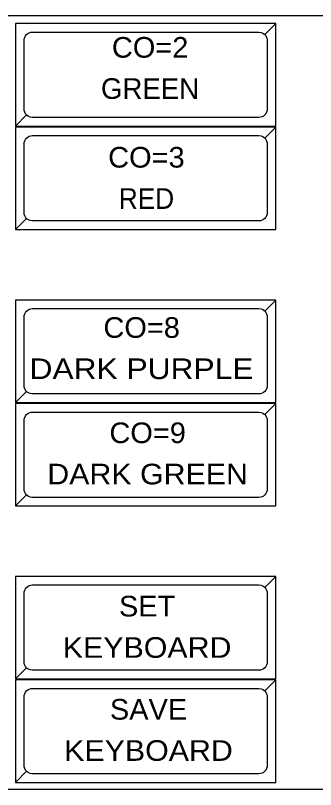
# Model space of a CAD drawing. Extents: x 16898 to 16911.6, y 15837.8 to 15842.
# Drawn here: x 16902.171 to 16902.962, y 15839.972 to 15842.012 of the extents above; entities that cross this region are included whole.
import ezdxf
from ezdxf.enums import TextEntityAlignment as Align

# ---------------------------------------------------------------- set-up
doc = ezdxf.new("R2010")
doc.units = 0
doc.header["$LTSCALE"] = 0.018
for name, color, linetype, lineweight in [('1', 7, 'Continuous', 25), ('2', 7, 'Continuous', 13), ('5', 7, 'Continuous', 13)]:
    doc.layers.add(name, color=color, linetype=linetype, lineweight=lineweight)

msp = doc.modelspace()

# ---------------------------------------------------------------- linework, layer by layer
at = {"layer": '1'}
for points in [[(16897.9955, 15839.9723), (16897.9955, 15842.0124), (16911.4764, 15842.0124), (16911.5674, 15841.9251), (16911.5674, 15840.0599), (16911.4764, 15839.9723)], [(16902.1709, 15841.7211), (16902.8573, 15841.7211), (16902.8573, 15841.9911), (16902.1709, 15841.9911)], [(16902.1709, 15841.7211), (16902.8573, 15841.7211), (16902.8573, 15841.9911), (16902.8282, 15841.962), (16902.831, 15841.9586), (16902.8331, 15841.9547), (16902.8343, 15841.9505), (16902.8348, 15841.9461), (16902.8348, 15841.7661), (16902.8343, 15841.7617), (16902.8331, 15841.7575), (16902.831, 15841.7536), (16902.8282, 15841.7502), (16902.8282, 15841.7502), (16902.8248, 15841.7474), (16902.8209, 15841.7453), (16902.8167, 15841.744), (16902.8123, 15841.7436), (16902.2159, 15841.7436), (16902.2093, 15841.7446), (16902.2053, 15841.7463), (16902.2016, 15841.7487), (16902.2, 15841.7502)], [(16902.8573, 15841.9911), (16902.1709, 15841.9911), (16902.1709, 15841.7211), (16902.2, 15841.7502), (16902.1972, 15841.7536), (16902.1951, 15841.7575), (16902.1938, 15841.7617), (16902.1934, 15841.7661), (16902.1934, 15841.9461), (16902.1938, 15841.9505), (16902.1951, 15841.9547), (16902.1972, 15841.9586), (16902.2, 15841.962), (16902.2, 15841.962), (16902.2034, 15841.9648), (16902.2073, 15841.9669), (16902.2115, 15841.9681), (16902.2159, 15841.9686), (16902.8123, 15841.9686), (16902.8189, 15841.9676), (16902.8229, 15841.9659), (16902.8266, 15841.9635), (16902.8282, 15841.962)], [(16902.1709, 15841.4483), (16902.8573, 15841.4483), (16902.8573, 15841.7183), (16902.1709, 15841.7183)], [(16902.1709, 15841.4483), (16902.8573, 15841.4483), (16902.8573, 15841.7183), (16902.8282, 15841.6892), (16902.831, 15841.6858), (16902.8331, 15841.6819), (16902.8343, 15841.6777), (16902.8348, 15841.6733), (16902.8348, 15841.4933), (16902.8343, 15841.4889), (16902.8331, 15841.4847), (16902.831, 15841.4808), (16902.8282, 15841.4774), (16902.8282, 15841.4774), (16902.8248, 15841.4746), (16902.8209, 15841.4725), (16902.8167, 15841.4712), (16902.8123, 15841.4708), (16902.2159, 15841.4708), (16902.2093, 15841.4718), (16902.2053, 15841.4735), (16902.2016, 15841.4759), (16902.2, 15841.4774)], [(16902.8573, 15841.7183), (16902.1709, 15841.7183), (16902.1709, 15841.4483), (16902.2, 15841.4774), (16902.1972, 15841.4808), (16902.1951, 15841.4847), (16902.1938, 15841.4889), (16902.1934, 15841.4933), (16902.1934, 15841.6733), (16902.1938, 15841.6777), (16902.1951, 15841.6819), (16902.1972, 15841.6858), (16902.2, 15841.6892), (16902.2, 15841.6892), (16902.2034, 15841.692), (16902.2073, 15841.6941), (16902.2115, 15841.6953), (16902.2159, 15841.6958), (16902.8123, 15841.6958), (16902.8189, 15841.6948), (16902.8229, 15841.6931), (16902.8266, 15841.6907), (16902.8282, 15841.6892)], [(16902.1709, 15840.9924), (16902.8573, 15840.9924), (16902.8573, 15841.2624), (16902.1709, 15841.2624)], [(16902.1709, 15840.9924), (16902.8573, 15840.9924), (16902.8573, 15841.2624), (16902.8282, 15841.2333), (16902.831, 15841.2299), (16902.8331, 15841.226), (16902.8343, 15841.2218), (16902.8348, 15841.2174), (16902.8348, 15841.0374), (16902.8343, 15841.033), (16902.8331, 15841.0288), (16902.831, 15841.0249), (16902.8282, 15841.0215), (16902.8282, 15841.0215), (16902.8248, 15841.0187), (16902.8209, 15841.0166), (16902.8167, 15841.0153), (16902.8123, 15841.0149), (16902.2159, 15841.0149), (16902.2093, 15841.0159), (16902.2053, 15841.0176), (16902.2016, 15841.02), (16902.2, 15841.0215)], [(16902.8573, 15841.2624), (16902.1709, 15841.2624), (16902.1709, 15840.9924), (16902.2, 15841.0215), (16902.1972, 15841.0249), (16902.1951, 15841.0288), (16902.1938, 15841.033), (16902.1934, 15841.0374), (16902.1934, 15841.2174), (16902.1938, 15841.2218), (16902.1951, 15841.226), (16902.1972, 15841.2299), (16902.2, 15841.2333), (16902.2, 15841.2333), (16902.2034, 15841.2361), (16902.2073, 15841.2382), (16902.2115, 15841.2394), (16902.2159, 15841.2399), (16902.8123, 15841.2399), (16902.8189, 15841.2389), (16902.8229, 15841.2372), (16902.8266, 15841.2348), (16902.8282, 15841.2333)], [(16902.1709, 15840.7196), (16902.8573, 15840.7196), (16902.8573, 15840.9896), (16902.1709, 15840.9896)], [(16902.1709, 15840.7196), (16902.8573, 15840.7196), (16902.8573, 15840.9896), (16902.8282, 15840.9605), (16902.831, 15840.9571), (16902.8331, 15840.9532), (16902.8343, 15840.949), (16902.8348, 15840.9446), (16902.8348, 15840.7646), (16902.8343, 15840.7602), (16902.8331, 15840.756), (16902.831, 15840.7521), (16902.8282, 15840.7487), (16902.8282, 15840.7487), (16902.8248, 15840.7459), (16902.8209, 15840.7438), (16902.8167, 15840.7425), (16902.8123, 15840.7421), (16902.2159, 15840.7421), (16902.2093, 15840.7431), (16902.2053, 15840.7448), (16902.2016, 15840.7472), (16902.2, 15840.7487)], [(16902.8573, 15840.9896), (16902.1709, 15840.9896), (16902.1709, 15840.7196), (16902.2, 15840.7487), (16902.1972, 15840.7521), (16902.1951, 15840.756), (16902.1938, 15840.7602), (16902.1934, 15840.7646), (16902.1934, 15840.9446), (16902.1938, 15840.949), (16902.1951, 15840.9532), (16902.1972, 15840.9571), (16902.2, 15840.9605), (16902.2, 15840.9605), (16902.2034, 15840.9633), (16902.2073, 15840.9654), (16902.2115, 15840.9666), (16902.2159, 15840.9671), (16902.8123, 15840.9671), (16902.8189, 15840.9661), (16902.8229, 15840.9644), (16902.8266, 15840.962), (16902.8282, 15840.9605)], [(16902.1709, 15840.264), (16902.8573, 15840.264), (16902.8573, 15840.534), (16902.1709, 15840.534)], [(16902.1709, 15840.264), (16902.8573, 15840.264), (16902.8573, 15840.534), (16902.8282, 15840.5049), (16902.831, 15840.5015), (16902.8331, 15840.4976), (16902.8343, 15840.4934), (16902.8348, 15840.489), (16902.8348, 15840.309), (16902.8343, 15840.3046), (16902.8331, 15840.3004), (16902.831, 15840.2965), (16902.8282, 15840.2931), (16902.8282, 15840.2931), (16902.8248, 15840.2903), (16902.8209, 15840.2882), (16902.8167, 15840.2869), (16902.8123, 15840.2865), (16902.2159, 15840.2865), (16902.2093, 15840.2875), (16902.2053, 15840.2892), (16902.2016, 15840.2916), (16902.2, 15840.2931)], [(16902.8573, 15840.534), (16902.1709, 15840.534), (16902.1709, 15840.264), (16902.2, 15840.2931), (16902.1972, 15840.2965), (16902.1951, 15840.3004), (16902.1938, 15840.3046), (16902.1934, 15840.309), (16902.1934, 15840.489), (16902.1938, 15840.4934), (16902.1951, 15840.4976), (16902.1972, 15840.5015), (16902.2, 15840.5049), (16902.2, 15840.5049), (16902.2034, 15840.5077), (16902.2073, 15840.5098), (16902.2115, 15840.511), (16902.2159, 15840.5115), (16902.8123, 15840.5115), (16902.8189, 15840.5105), (16902.8229, 15840.5088), (16902.8266, 15840.5064), (16902.8282, 15840.5049)], [(16902.1709, 15839.9912), (16902.8573, 15839.9912), (16902.8573, 15840.2612), (16902.1709, 15840.2612)], [(16902.1709, 15839.9912), (16902.8573, 15839.9912), (16902.8573, 15840.2612), (16902.8282, 15840.2321), (16902.831, 15840.2287), (16902.8331, 15840.2248), (16902.8343, 15840.2206), (16902.8348, 15840.2162), (16902.8348, 15840.0362), (16902.8343, 15840.0318), (16902.8331, 15840.0276), (16902.831, 15840.0237), (16902.8282, 15840.0203), (16902.8282, 15840.0203), (16902.8248, 15840.0175), (16902.8209, 15840.0154), (16902.8167, 15840.0141), (16902.8123, 15840.0137), (16902.2159, 15840.0137), (16902.2093, 15840.0147), (16902.2053, 15840.0164), (16902.2016, 15840.0188), (16902.2, 15840.0203)], [(16902.8573, 15840.2612), (16902.1709, 15840.2612), (16902.1709, 15839.9912), (16902.2, 15840.0203), (16902.1972, 15840.0237), (16902.1951, 15840.0276), (16902.1938, 15840.0318), (16902.1934, 15840.0362), (16902.1934, 15840.2162), (16902.1938, 15840.2206), (16902.1951, 15840.2248), (16902.1972, 15840.2287), (16902.2, 15840.2321), (16902.2, 15840.2321), (16902.2034, 15840.2349), (16902.2073, 15840.237), (16902.2115, 15840.2382), (16902.2159, 15840.2387), (16902.8123, 15840.2387), (16902.8189, 15840.2377), (16902.8229, 15840.236), (16902.8266, 15840.2336), (16902.8282, 15840.2321)]]:
    msp.add_lwpolyline(points, close=True, dxfattribs=at)
at = {"layer": '2'}
msp.add_lwpolyline([(16897.9955, 15839.9723), (16897.9955, 15842.0124), (16911.4764, 15842.0124), (16911.5674, 15841.9251), (16911.5674, 15840.0599), (16911.4764, 15839.9723)], close=True, dxfattribs=at)

# ---------------------------------------------------------------- texts
at = {"layer": '5'}
for s, width, p in [('CO=2', 1.05, (16902.5259, 15841.9012)), ('CO=3', 1.05, (16902.5161, 15841.6115)), ('RED', 0.95, (16902.5163, 15841.5027)), ('CO=8', 1.05, (16902.5036, 15841.1628)), ('DARK PURPLE', 1.15, (16902.5032, 15841.0541)), ('CO=9', 1.05, (16902.5194, 15840.8853)), ('DARK GREEN', 1.1, (16902.5193, 15840.7765)), ('SET', 1.05, (16902.518, 15840.4284)), ('KEYBOARD', 1.1, (16902.518, 15840.3194)), ('SAVE', 1.05, (16902.5217, 15840.1565)), ('KEYBOARD', 1.1, (16902.5216, 15840.0479))]:
    msp.add_text(s, height=0.0544, dxfattribs=dict(at, width=width)).set_placement(p, align=Align.CENTER)
msp.add_text('GREEN', height=0.0544, dxfattribs=at).set_placement((16902.5257, 15841.7926), align=Align.CENTER)

doc.saveas('drawing.dxf')
